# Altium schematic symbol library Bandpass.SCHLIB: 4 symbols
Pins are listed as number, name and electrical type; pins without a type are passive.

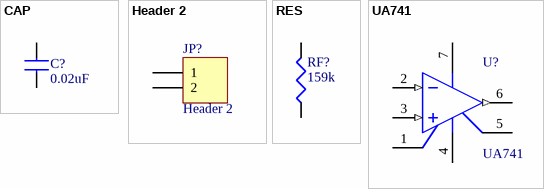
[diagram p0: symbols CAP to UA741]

## CAP
designator C?, comment 0.02uF
Capacitor
simulation model CAP
pins: 1, 2

## Header 2
designator JP?
Header, 2-Pin; Manufacturer: Generic Components; Class I: Connector
footprint HDR1X2
signal-integrity model Connector
pins: 1, 2

## RES
designator RF?, comment 159k
Resistor
simulation model RESISTOR
pins: 1 TOP, 2 BOT

## UA741
designator U?
General-Purpose Operational Amplifier
simulation model UA741 (SUBCKT)
pins: 1 OFFSET NULL 1, 2 -IN (in), 3 +IN (in), 4 V- (power), 5 OFFSET NULL 2, 6 OUT (out), 7 V+ (power)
